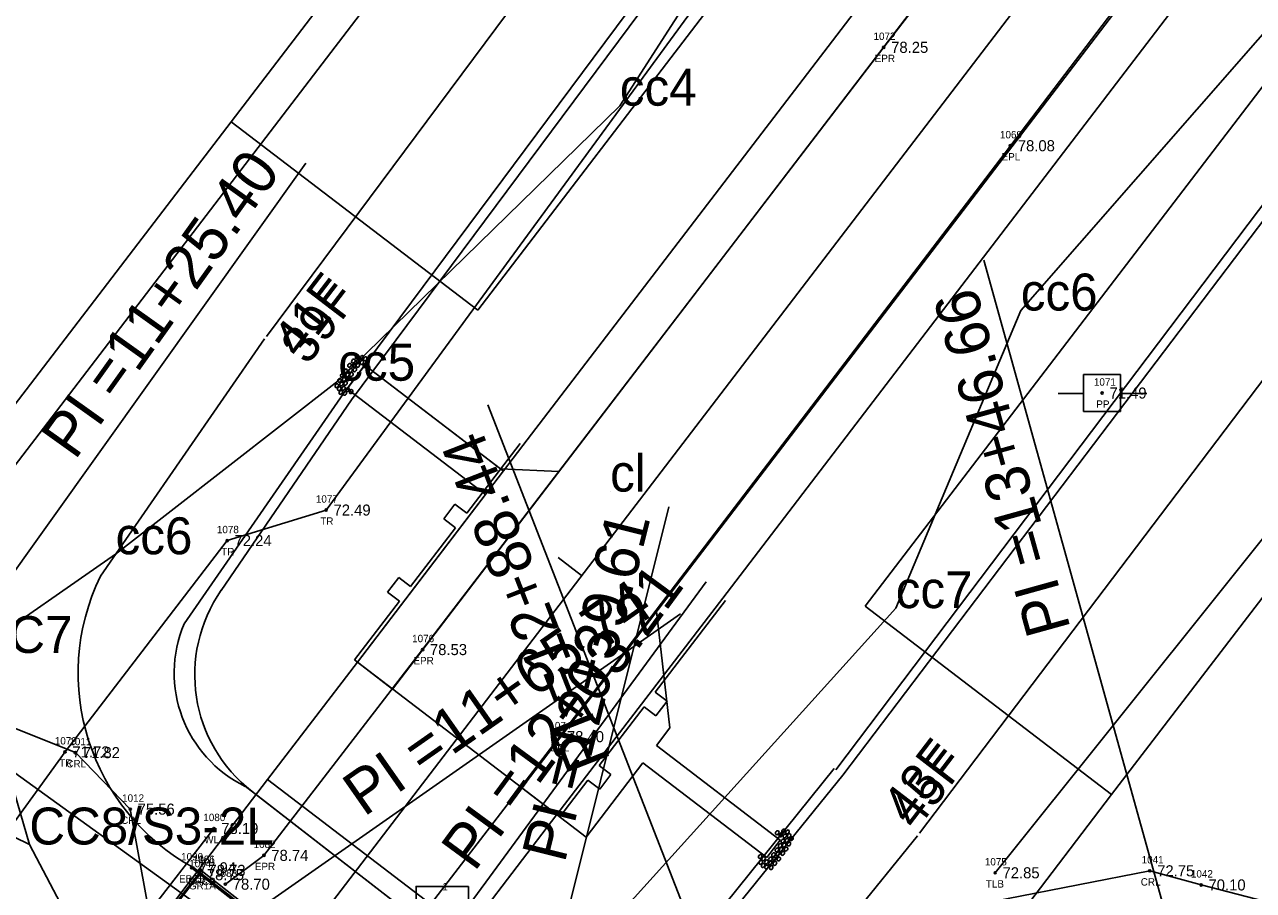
# Model space of a CAD drawing. Extents: x 2500794 to 2511032, y 910653 to 917533.
# Drawn here: x 2505787 to 2505953.3, y 913541.8 to 913659 of the extents above; entities that cross this region are included whole.
import ezdxf

# ---------------------------------------------------------------- set-up
doc = ezdxf.new("R2010")
doc.units = 0
for name, color, linetype in [('Default', 7, 'Continuous'), ('RD_EX_Bridge', 7, 'Continuous'), ('RD_EX_Bridge_txCode', 7, 'Continuous'), ('RD_EX_GuardRail', 7, 'Continuous'), ('RD_EX_GuardRail_txCode', 7, 'Continuous'), ('RD_EX_H2O', 7, 'Continuous'), ('RD_EX_H2O_txCode', 7, 'Continuous'), ('RD_EX_H2O_WetLd', 7, 'Continuous'), ('RD_EX_Road', 7, 'Continuous'), ('RD_EX_Road_txCode', 7, 'Continuous'), ('RD_EX_RW', 7, 'Continuous'), ('RD_EX_TX_Bridge_ELEV', 7, 'Continuous'), ('RD_EX_TX_GuardRail_ELEV', 7, 'Continuous'), ('RD_EX_TX_H2O_ELEV', 7, 'Continuous'), ('RD_EX_TX_Road_ELEV', 7, 'Continuous'), ('RD_EX_TX_UT_ELEV', 7, 'Continuous'), ('RD_EX_TX_VEG_ELEV', 7, 'Continuous'), ('RD_EX_UT', 7, 'Continuous'), ('RD_EX_UT_txCode', 7, 'Continuous'), ('RD_EX_VEG', 7, 'Continuous'), ('RD_EX_VEG_txCode', 7, 'Continuous'), ('RD_HC_Cl', 7, 'Continuous'), ('RD_HC_Data', 7, 'Continuous'), ('RD_HC_Data_Tic', 7, 'Continuous'), ('RD_HC_Survey', 7, 'Continuous'), ('RD_HC_Survey_ELEV', 7, 'Continuous'), ('RD_HC_Survey_txCode', 7, 'Continuous'), ('RD_PD_ALT1_TrvlWay', 7, 'Continuous'), ('RD_PD_BCA', 7, 'Continuous'), ('RD_PD_Bridge', 7, 'Continuous'), ('RD_PD_CstnLmt', 7, 'Continuous'), ('RD_PD_CstnLmt_TX', 7, 'Continuous'), ('RD_PD_DitchBtm', 7, 'Continuous'), ('RD_PD_GR', 7, 'Continuous'), ('RD_PD_PaveShd', 7, 'Continuous'), ('RD_PD_RW', 7, 'Continuous'), ('RD_PD_Signals', 7, 'Continuous'), ('RD_Sketch10', 7, 'Continuous'), ('RD_SMD_Locator', 7, 'Continuous'), ('RD_XS_NPDES', 7, 'Continuous')]:
    doc.layers.add(name, color=color, linetype=linetype)

# ---------------------------------------------------------------- blocks, each defined once
blk = doc.blocks.new('POINT_DISPLAY')
at = {"layer": 'Default'}
blk.add_line((0, 0), (0, 0), dxfattribs=at)
blk = doc.blocks.new('Non-Wetland Waters (Tributaries)')
at = {"layer": 'Default'}
blk.add_lwpolyline([(636472.197, 232037.165), (636470.066, 232041.194), (636461.608, 232045.336), (636444.397, 232053.387), (636441.101, 232054.059)], dxfattribs=at)
blk = doc.blocks.new('Wetlands')
at = {"layer": 'Default'}
for points in [[(636520.194, 232111.184), (636514.488, 232100.701), (636499.967, 232081.539), (636490.363, 232066.6), (636480.685, 232057.143), (636473.031, 232051.175), (636468.151, 232047.782), (636470.066, 232041.194), (636461.608, 232045.336), (636444.397, 232053.387), (636441.101, 232054.059), (636484.137, 232110.659), (636486.079, 232110.274), (636502.502, 232110.709), (636520.194, 232111.184)], [(636578.378, 232108.026), (636523.855, 232037.448), (636501.371, 232037.816), (636484.456, 232032.271), (636499.849, 232049.322), (636504.147, 232059.556), (636518.345, 232075.791), (636532.382, 232092.673), (636539.146, 232087.393), (636544.708, 232099.914), (636554.736, 232107.733), (636570.529, 232108.061), (636578.378, 232108.026)]]:
    blk.add_lwpolyline(points, dxfattribs=at)

msp = doc.modelspace()

# ---------------------------------------------------------------- linework, layer by layer
at = {"layer": 'RD_EX_Bridge'}
msp.add_line((2505835.88, 913524.37), (2505809.62, 913544.86), dxfattribs=at)
msp.add_lwpolyline([(2505810.9, 913544.51), (2505835.38, 913525.37), (2505780.21, 913454.04), (2505755.58, 913473.5), (2505810.9, 913544.51)], dxfattribs=at)
at = {"layer": 'RD_EX_GuardRail'}
msp.add_line((2505810.69, 913543.93), (2505755.9, 913473.88), dxfattribs=at)
at = {"layer": 'RD_EX_H2O_txCode'}
msp.add_lwpolyline([(2505762.26, 913658.11), (2505746.15, 913644.25), (2505726.47, 913615.21), (2505674.21, 913628.01), (2505666.25, 913620.58), (2505714.6, 913592.15), (2505793.9, 913560.45), (2505801.32, 913552.8), (2505803.7, 913539.77), (2505832.63, 913516.96), (2505848.42, 913517.19), (2505881.86, 913528.44), (2505910.2, 913538.78), (2505939.3, 913544.45), (2505946.25, 913542.54), (2505974.65, 913535.18), (2506004.11, 913524.7), (2506052.03, 913515.47), (2506115.49, 913494.68), (2506138.05, 913548.89)], dxfattribs=at)
at = {"layer": 'RD_EX_Road'}
for points in [[(2506024.03, 913813.1), (2505962.01, 913732.06), (2505903.3, 913655.93), (2505840.88, 913574.4), (2505819.41, 913546.54), (2505814.19, 913542.64)], [(2506040.71, 913800.23), (2505979.73, 913720.47), (2505920.44, 913642.61), (2505859.42, 913562.61), (2505835.44, 913531.43), (2505833.77, 913527.25)]]:
    msp.add_lwpolyline(points, dxfattribs=at)
at = {"layer": 'RD_EX_RW'}
for p, q in [((2505848.34, 913620.35), (2505988.03, 913803.07)), ((2505900.77, 913580.27), (2506040.47, 913762.98)), ((2505742.31, 913550.82), (2505814.97, 913645.86)), ((2505814.97, 913645.86), (2505848.34, 913620.35)), ((2505900.77, 913580.27), (2505934.14, 913554.76)), ((2505867.15, 913467.14), (2505934.14, 913554.76))]:
    msp.add_line(p, q, dxfattribs=at)
at = {"layer": 'RD_EX_UT'}
for p, q in [((2505935.34, 913611.64), (2505930.34, 913611.64)), ((2505930.34, 913611.64), (2505930.34, 913606.64)), ((2505935.34, 913606.64), (2505935.34, 913611.64)), ((2505926.91, 913609.08), (2505930.38, 913609.08)), ((2505935.27, 913609.08), (2505938.91, 913609.08)), ((2505930.34, 913606.64), (2505935.34, 913606.64)), ((2505812.64, 913550.18), (2505751.54, 913471.47))]:
    msp.add_line(p, q, dxfattribs=at)
at = {"layer": 'RD_EX_VEG'}
for points in [[(2506002.64, 913815.25), (2505883.7, 913669.64), (2505827.83, 913593.29), (2505814.43, 913589.15), (2505792.49, 913560.55), (2505725.64, 913468.24), (2505664.37, 913399.09), (2505478.33, 913221), (2505411.99, 913152.19), (2505339.13, 913074.53)], [(2506132.67, 913791.11), (2506063.24, 913729.37), (2505966.14, 913603.86), (2505918.37, 913544.18)]]:
    msp.add_lwpolyline(points, dxfattribs=at)
at = {"layer": 'RD_HC_Cl'}
msp.add_line((2505807.57, 913512.69), (2506748.89, 914743.92), dxfattribs=at)
at = {"layer": 'RD_HC_Data'}
for p, q in [((2505757.7, 913545.85), (2505825.06, 913640.23)), ((2505947.94, 913515.14), (2505916.85, 913627.1)), ((2505891.84, 913499.56), (2505849.73, 913607.54)), ((2505846.35, 913481.82), (2505874.19, 913593.73)), ((2505811.03, 913490.61), (2505879.28, 913583.56)), ((2505780.82, 913512.79), (2505875.8, 913579.22))]:
    msp.add_line(p, q, dxfattribs=at)
at = {"layer": 'RD_HC_Data_Tic'}
msp.add_line((2505862.41, 913584.42), (2505859.23, 913586.85), dxfattribs=at)
at = {"layer": 'RD_HC_Survey'}
msp.add_lwpolyline([(2505847.08, 913542.34), (2505840.01, 913542.34), (2505840.01, 913535.27), (2505847.08, 913535.27)], close=True, dxfattribs=at)
at = {"layer": 'RD_PD_ALT1_TrvlWay'}
for p, q in [((2505836.82, 913569.06), (2505999.71, 913782.11)), ((2505854.3, 913555.7), (2506017.18, 913768.75))]:
    msp.add_line(p, q, dxfattribs=at)
at = {"layer": 'RD_PD_BCA'}
for p, q in [((2505765.19, 913572.52), (2505977.56, 913850.28)), ((2505822.03, 913531.5), (2505765.19, 913572.52))]:
    msp.add_line(p, q, dxfattribs=at)
at = {"layer": 'RD_PD_Bridge'}
for p, q in [((2505819.91, 913556.82), (2505832.06, 913572.71)), ((2505859.07, 913552.06), (2505832.06, 913572.71)), ((2505794.06, 913523.02), (2505819.91, 913556.82)), ((2505846.92, 913536.17), (2505819.91, 913556.82)), ((2505846.92, 913536.17), (2505859.07, 913552.06))]:
    msp.add_line(p, q, dxfattribs=at)
at = {"layer": 'RD_PD_CstnLmt'}
for p, q in [((2505830.2, 913609.05), (2505889.87, 913689.3)), ((2505897.77, 913557.38), (2505958.15, 913637.1)), ((2505808.63, 913577.89), (2505830.2, 913609.05)), ((2505878.36, 913533.44), (2505897.77, 913557.38)), ((2505850.07, 913530.22), (2505816.89, 913555.89))]:
    msp.add_line(p, q, dxfattribs=at)
msp.add_arc((2505824.32, 913571.23), 17.05, 157.0035, 244.1745, dxfattribs=at)
at = {"layer": 'RD_PD_DitchBtm'}
for p, q in [((2505854.3, 913555.7), (2505872.52, 913579.54)), ((2505872.52, 913579.54), (2505854.3, 913555.7)), ((2505874.35, 913563.82), (2505872.52, 913579.54)), ((2505874.35, 913563.82), (2505872.52, 913579.54)), ((2505872.53, 913561.43), (2505874.35, 913563.82)), ((2505872.53, 913561.43), (2505874.35, 913563.82)), ((2505889.29, 913548.62), (2505872.53, 913561.43)), ((2505889.29, 913548.62), (2505872.53, 913561.43)), ((2505863.04, 913549.02), (2505870.71, 913559.05)), ((2505863.04, 913549.02), (2505870.71, 913559.05)), ((2505887.48, 913546.23), (2505870.71, 913559.05)), ((2505870.71, 913559.05), (2505887.48, 913546.23)), ((2505863.04, 913549.02), (2505854.3, 913555.7)), ((2505854.3, 913555.7), (2505863.04, 913549.02)), ((2505887.48, 913546.23), (2505889.29, 913548.62)), ((2505887.48, 913546.23), (2505889.29, 913548.62))]:
    msp.add_line(p, q, dxfattribs=at)
for centre in [(2505888.89, 913549.61), (2505889.35, 913549.31), (2505889.73, 913549.83), (2505889.91, 913549.18), (2505890.27, 913549.72), (2505890.48, 913549.21), (2505889.26, 913547.86), (2505889.64, 913548.5), (2505889.83, 913547.94), (2505890.18, 913548.56), (2505890.46, 913548.08), (2505890.81, 913548.8), (2505886.57, 913546.39), (2505887.04, 913546.09), (2505887.95, 913546.04), (2505888.37, 913546.63), (2505888.47, 913546.06), (2505888.84, 913547.28), (2505888.95, 913546.73), (2505889.1, 913546.05), (2505889.4, 913547.34), (2505889.64, 913546.8), (2505890.07, 913547.4), (2505886.66, 913545.59), (2505886.97, 913545.17), (2505887.41, 913545.65), (2505887.43, 913544.98), (2505887.97, 913545.49), (2505888.07, 913544.89), (2505888.57, 913545.46)]:
    msp.add_ellipse(centre, major_axis=(0.154, 0.243), ratio=0.739412, dxfattribs=at)
at = {"layer": 'RD_PD_GR'}
for p, q in [((2505854.47, 913602.02), (2505972.53, 913756.44)), ((2505881.5, 913581.36), (2505999.52, 913735.81)), ((2505832.06, 913572.71), (2505854.47, 913602.02)), ((2505854.08, 913602.32), (2505846.85, 913592.87)), ((2505845.25, 913594.09), (2505843.74, 913592.1)), ((2505846.85, 913592.87), (2505845.25, 913594.09)), ((2505843.74, 913592.1), (2505845.33, 913590.88)), ((2505845.33, 913590.88), (2505839.26, 913582.94)), ((2505837.66, 913584.16), (2505836.14, 913582.17)), ((2505839.26, 913582.94), (2505837.66, 913584.16)), ((2505836.14, 913582.17), (2505837.74, 913580.95)), ((2505881.5, 913581.36), (2505859.07, 913552.06)), ((2505872.37, 913568.63), (2505881.89, 913581.05)), ((2505837.74, 913580.95), (2505831.66, 913573.01)), ((2505831.66, 913573.01), (2505832.06, 913572.71)), ((2505873.97, 913567.41), (2505872.37, 913568.63)), ((2505864.78, 913558.71), (2505870.85, 913566.65)), ((2505870.85, 913566.65), (2505872.45, 913565.43)), ((2505872.45, 913565.43), (2505873.97, 913567.41)), ((2505866.37, 913557.49), (2505864.78, 913558.71)), ((2505859.46, 913551.76), (2505863.26, 913556.72)), ((2505863.26, 913556.72), (2505864.85, 913555.5)), ((2505864.85, 913555.5), (2505866.37, 913557.49)), ((2505859.07, 913552.06), (2505859.46, 913551.76))]:
    msp.add_line(p, q, dxfattribs=at)
at = {"layer": 'RD_PD_PaveShd'}
for p, q in [((2505833.06, 913612.9), (2505830.67, 913609.69)), ((2505833.06, 913612.9), (2505851.82, 913598.56)), ((2505851.43, 913598.86), (2505833.06, 913612.9)), ((2505830.67, 913609.69), (2505849.39, 913595.38)), ((2505830.67, 913609.69), (2505849.39, 913595.38)), ((2505859.32, 913598.49), (2505836.82, 913569.06)), ((2505851.43, 913598.86), (2505859.32, 913598.49)), ((2505859.32, 913598.49), (2505851.43, 913598.86)), ((2505832.06, 913572.71), (2505849.39, 913595.38)), ((2505849.39, 913595.38), (2505832.06, 913572.71)), ((2505836.82, 913569.06), (2505832.06, 913572.71)), ((2505832.06, 913572.71), (2505836.78, 913569.09))]:
    msp.add_line(p, q, dxfattribs=at)
msp.add_lwpolyline([(2505836.78, 913569.09), (2505840.88, 913574.4), (2505859.32, 913598.49)], dxfattribs=at)
at = {"layer": 'RD_PD_RW'}
for p, q in [((2505814.97, 913645.86), (2505954.67, 913828.58)), ((2505934.14, 913554.76), (2506073.83, 913737.47))]:
    msp.add_line(p, q, dxfattribs=at)
at = {"layer": 'RD_PD_Signals'}
for p, q in [((2505831.28, 913608.22), (2505890.97, 913688.46)), ((2505896.79, 913558.14), (2505957.08, 913637.92)), ((2505813.64, 913582.42), (2505831.28, 913608.22)), ((2505877.09, 913534.1), (2505896.59, 913558.29)), ((2505849.28, 913530.83), (2505817.81, 913555.18))]:
    msp.add_line(p, q, dxfattribs=at)
msp.add_arc((2505830.05, 913571), 20, 145.1503, 232.2705, dxfattribs=at)
at = {"layer": 'RD_Sketch10'}
for centre in [(2505832.02, 913614.04), (2505830.99, 913612.88), (2505831.52, 913613.46), (2505831.62, 913612.87), (2505831.72, 913612.29), (2505832.12, 913613.44), (2505832.14, 913612.88), (2505832.66, 913613.94), (2505832.68, 913613.28), (2505833.05, 913612.84), (2505833.12, 913613.76), (2505833.43, 913613.34), (2505833.52, 913612.53), (2505829.64, 913610.85), (2505830.02, 913611.53), (2505830.26, 913610.99), (2505830.45, 913612.12), (2505830.7, 913611.59), (2505830.83, 913611.07), (2505831.14, 913612.2), (2505831.25, 913611.64), (2505829.28, 913610.12), (2505829.61, 913609.72), (2505829.82, 913609.21), (2505829.91, 913610.37), (2505830.18, 913609.75), (2505830.36, 913609.1), (2505830.45, 913610.43), (2505830.74, 913609.61), (2505831.2, 913609.32)]:
    msp.add_ellipse(centre, major_axis=(-0.154, -0.243), ratio=0.739412, dxfattribs=at)
at = {"layer": 'RD_SMD_Locator'}
for centre in [(2505903.3, 913655.93), (2505920.44, 913642.61), (2505932.85, 913609.13), (2505827.83, 913593.29), (2505814.43, 913589.15), (2505840.88, 913574.4), (2505859.42, 913562.61), (2505792.49, 913560.55), (2505793.9, 913560.45), (2505801.32, 913552.8), (2505812.64, 913550.18), (2505819.41, 913546.54), (2505809.62, 913544.86), (2505810.9, 913544.51), (2505810.9, 913544.51), (2505939.3, 913544.45), (2505810.69, 913543.93), (2505814.19, 913542.64), (2505918.37, 913544.18), (2505946.25, 913542.54)]:
    msp.add_circle(centre, 0.15, dxfattribs=at)
at = {"layer": 'RD_XS_NPDES'}
for p, q in [((2505819.77, 913616.8), (2505879.44, 913697.06)), ((2505908.14, 913549.53), (2505968.51, 913629.25)), ((2505797.29, 913584.35), (2505819.51, 913616.45)), ((2505884.04, 913519.8), (2505907.87, 913549.2)), ((2505841.33, 913520.55), (2505809.86, 913544.9))]:
    msp.add_line(p, q, dxfattribs=at)
msp.add_arc((2505824.32, 913571.23), 30.05, 154.1096, 241.2298, dxfattribs=at)

# ---------------------------------------------------------------- block references
at = {"layer": 'Default', "xscale": 3.937007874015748, "yscale": 3.937007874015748}
for name, p in [('Wetlands', (0, 0)), ('Non-Wetland Waters (Tributaries)', (0, 0)), ('POINT_DISPLAY', (2505867.57, 913648.03)), ('POINT_DISPLAY', (2505867.57, 913648.03)), ('POINT_DISPLAY', (2505921.84, 913620.3)), ('POINT_DISPLAY', (2505921.84, 913620.3)), ('POINT_DISPLAY', (2505829.47, 913610.8)), ('POINT_DISPLAY', (2505829.47, 913610.8)), ('POINT_DISPLAY', (2505866.26, 913595.79)), ('POINT_DISPLAY', (2505866.26, 913595.79)), ('POINT_DISPLAY', (2505799.33, 913587.3)), ('POINT_DISPLAY', (2505799.33, 913587.3)), ('POINT_DISPLAY', (2505904.92, 913580.01)), ('POINT_DISPLAY', (2505904.92, 913580.01)), ('POINT_DISPLAY', (2505787.66, 913548.01)), ('POINT_DISPLAY', (2505787.66, 913548.01))]:
    msp.add_blockref(name, p, dxfattribs=at)
at = {"layer": 'RD_EX_H2O', "xscale": 3.937007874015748, "yscale": 3.937007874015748}
msp.add_blockref('Non-Wetland Waters (Tributaries)', (0, 0), dxfattribs=at)
at = {"layer": 'RD_EX_H2O_WetLd', "xscale": 3.937007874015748, "yscale": 3.937007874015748}
msp.add_blockref('Wetlands', (0, 0), dxfattribs=at)

# ---------------------------------------------------------------- texts
at = {"layer": 'Default'}
for s, p in [('cc4', (2505867.57, 913648.03)), ('cc4', (2505867.57, 913648.03)), ('cc6', (2505921.84, 913620.3)), ('cc6', (2505921.84, 913620.3)), ('cc5', (2505829.47, 913610.8)), ('cc5', (2505829.47, 913610.8)), ('cl', (2505866.26, 913595.79)), ('cl', (2505866.26, 913595.79)), ('cc6', (2505799.33, 913587.3)), ('cc6', (2505799.33, 913587.3)), ('cc7', (2505904.92, 913580.01)), ('cc7', (2505904.92, 913580.01)), ('CC7', (2505780.12, 913573.94)), ('CC7', (2505780.12, 913573.94)), ('CC8/S3-2L', (2505787.66, 913548.01)), ('CC8/S3-2L', (2505787.66, 913548.01))]:
    msp.add_text(s, height=5, dxfattribs=at).set_placement(p)
at = {"layer": 'RD_EX_Bridge_txCode'}
for s, p in [('1090', (2505808.2, 913545.86)), ('1106', (2505809.78, 913545.51)), ('1081', (2505809.8, 913545.51)), ('EBCB', (2505807.92, 913542.86)), ('BRCA', (2505809.16, 913542.51)), ('BRCB', (2505809.18, 913542.51))]:
    msp.add_text(s, height=1, dxfattribs=at).set_placement(p)
at = {"layer": 'RD_EX_GuardRail_txCode'}
for s, p in [('1084', (2505809.3, 913544.93)), ('GR1A', (2505809.26, 913541.93))]:
    msp.add_text(s, height=1, dxfattribs=at).set_placement(p)
at = {"layer": 'RD_EX_H2O_txCode'}
for s, p in [('1011', (2505793.08, 913561.45)), ('CRL', (2505792.67, 913558.45)), ('1012', (2505800.22, 913553.8)), ('CRL', (2505800.09, 913550.8)), ('1041', (2505938.2, 913545.45)), ('1042', (2505944.87, 913543.54)), ('CRL', (2505938.08, 913542.45))]:
    msp.add_text(s, height=1, dxfattribs=at).set_placement(p)
at = {"layer": 'RD_EX_Road_txCode'}
for s, p in [('1072', (2505901.91, 913656.93)), ('EPR', (2505902.07, 913653.93)), ('1069', (2505919.03, 913643.61)), ('EPL', (2505919.24, 913640.61)), ('1076', (2505839.47, 913575.4)), ('EPR', (2505839.65, 913572.4)), ('1074', (2505858.04, 913563.61)), ('EPL', (2505858.22, 913560.61)), ('1082', (2505818.02, 913547.54)), ('1083', (2505812.81, 913543.64)), ('EPR', (2505818.18, 913544.54))]:
    msp.add_text(s, height=1, dxfattribs=at).set_placement(p)
at = {"layer": 'RD_EX_TX_Bridge_ELEV'}
for s, p in [('77.94', (2505810.62, 913544.11)), ('78.73', (2505811.9, 913543.76)), ('78.73', (2505811.9, 913543.76))]:
    msp.add_text(s, height=1.5, dxfattribs=at).set_placement(p)
at = {"layer": 'RD_EX_TX_GuardRail_ELEV'}
msp.add_text('78.75', height=1.5, dxfattribs=at).set_placement((2505811.69, 913543.18))
at = {"layer": 'RD_EX_TX_H2O_ELEV'}
for s, p in [('71.82', (2505794.9, 913559.7)), ('75.56', (2505802.32, 913552.05)), ('72.75', (2505940.3, 913543.7)), ('70.10', (2505947.25, 913541.79))]:
    msp.add_text(s, height=1.5, dxfattribs=at).set_placement(p)
at = {"layer": 'RD_EX_TX_Road_ELEV'}
for s, p in [('78.25', (2505904.3, 913655.18)), ('78.08', (2505921.44, 913641.86)), ('78.53', (2505841.88, 913573.65)), ('78.40', (2505860.42, 913561.86)), ('78.74', (2505820.41, 913545.79)), ('78.70', (2505815.19, 913541.89))]:
    msp.add_text(s, height=1.5, dxfattribs=at).set_placement(p)
at = {"layer": 'RD_EX_TX_UT_ELEV'}
msp.add_text('78.19', height=1.5, dxfattribs=at).set_placement((2505813.64, 913549.43))
at = {"layer": 'RD_EX_TX_VEG_ELEV'}
for s, p in [('72.49', (2505828.83, 913592.54)), ('72.24', (2505815.43, 913588.4)), ('71.72', (2505793.49, 913559.8)), ('72.85', (2505919.37, 913543.43))]:
    msp.add_text(s, height=1.5, dxfattribs=at).set_placement(p)
at = {"layer": 'RD_EX_UT_txCode'}
for s, p in [('1071', (2505931.74, 913610.13)), ('PP', (2505932.07, 913607.13)), ('1080', (2505811.21, 913551.18)), ('WLA', (2505811.33, 913548.18))]:
    msp.add_text(s, height=1, dxfattribs=at).set_placement(p)
at = {"layer": 'RD_EX_VEG_txCode'}
for s, p in [('1077', (2505826.44, 913594.29)), ('1078', (2505813.04, 913590.15)), ('TR', (2505827.04, 913591.29)), ('TR', (2505813.63, 913587.15)), ('1079', (2505791.11, 913561.55)), ('TR', (2505791.7, 913558.55)), ('1075', (2505916.98, 913545.18)), ('TLB', (2505917.12, 913542.18))]:
    msp.add_text(s, height=1, dxfattribs=at).set_placement(p)
at = {"layer": 'RD_HC_Data'}
for s, rotation, p in [('PI =11+25.40', 54.4859, (2505793.83, 913599.92)), ('PI =13+46.66', 105.519, (2505928.62, 913577.24)), ('PI =12+88.44', 111.3052, (2505866.36, 913559.4)), ('PI =12+39.61', 76.0287, (2505860.1, 913545.38)), ('PI =12+03.21', 53.7099, (2505847.89, 913544.19)), ('PI =11+65.74', 34.9692, (2505832.94, 913551.68)), ('S 34%%d 58\' 09" E', 304.9692, (2505753.09, 913554.18))]:
    msp.add_text(s, height=6, rotation=rotation, dxfattribs=at).set_placement(p)
at = {"layer": 'RD_HC_Survey_ELEV'}
msp.add_text('71.49', height=1.5, dxfattribs=at).set_placement((2505933.85, 913608.38))
at = {"layer": 'RD_HC_Survey_txCode'}
msp.add_text('1', height=1, dxfattribs=at).set_placement((2505843.55, 913541.81))
at = {"layer": 'RD_PD_CstnLmt_TX'}
for s, p in [('41F', (2505824.24, 913613.6)), ('45F', (2505907.7, 913549.79))]:
    msp.add_text(s, height=5, rotation=52.6007, dxfattribs=at).set_placement(p)
at = {"layer": 'RD_PD_Signals'}
for s, p in [('39F', (2505825.32, 913612.78)), ('43F', (2505906.72, 913550.55))]:
    msp.add_text(s, height=5, rotation=52.6007, dxfattribs=at).set_placement(p)

doc.saveas('drawing.dxf')
